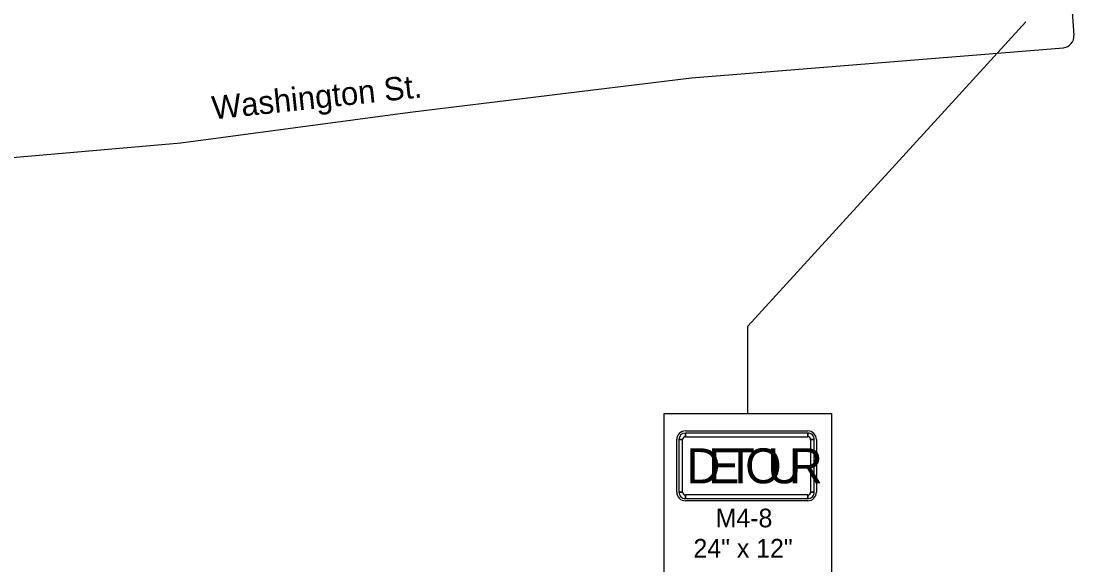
# Model space of a CAD drawing. Extents: x 10133 to 81668, y 6132 to 11018.
# Drawn here: x 11517.3 to 11970.2, y 8496.6 to 8730.4 of the extents above; entities that cross this region are included whole.
import ezdxf

# ---------------------------------------------------------------- set-up
doc = ezdxf.new("R2010")
doc.units = 0
for name, color, linetype in [('dsnTextFinalPlan', 7, 'Continuous'), ('Level 10', 7, 'Continuous'), ('Level 2', 7, 'Continuous'), ('Level 5', 7, 'Continuous')]:
    doc.layers.add(name, color=color, linetype=linetype)

msp = doc.modelspace()

# ---------------------------------------------------------------- linework, layer by layer
at = {"layer": 'dsnTextFinalPlan'}
for points in [[(11924.53, 9208.75), (11924.53, 9205.04), (11938.44, 9064.44), (11960.57, 8858.09), (11970.22, 8724.25)], [(11829.93, 8561.72), (11829.93, 8599.23), (11949.48, 8730.1)], [(10973.28, 8615.03), (11164.6, 8636.59), (11310.07, 8652.12), (11462.39, 8667.24), (11586.06, 8678), (11684.71, 8691.26), (11805.66, 8706.01), (11965.73, 8718.92)]]:
    msp.add_lwpolyline(points, dxfattribs=at)
msp.add_lwpolyline([(11793.9, 8561.72), (11865.97, 8561.72), (11865.97, 8249.49), (11793.9, 8249.49)], close=True, dxfattribs=at)
msp.add_lwpolyline([(11793.9, 8561.72), (11865.97, 8561.72), (11865.97, 8249.49), (11793.9, 8249.49)], close=True, dxfattribs=at)
msp.add_arc((11965.24, 8723.89), 5, 275.621, 4.1265, dxfattribs=at)
at = {"layer": 'Level 10'}
for p, q in [((11803.11, 8554.21), (11855.72, 8554.21)), ((11803.11, 8551.7), (11803.11, 8553.27)), ((11855.72, 8553.27), (11855.72, 8551.7)), ((11799.35, 8527.9), (11799.35, 8550.45)), ((11800.29, 8550.45), (11801.86, 8550.45)), ((11856.97, 8550.45), (11858.54, 8550.45)), ((11859.48, 8550.45), (11859.48, 8527.9)), ((11801.86, 8527.9), (11800.29, 8527.9)), ((11803.11, 8525.08), (11803.11, 8526.65)), ((11855.72, 8526.65), (11855.72, 8525.08)), ((11858.54, 8527.9), (11856.97, 8527.9)), ((11855.72, 8524.14), (11803.11, 8524.14))]:
    msp.add_line(p, q, dxfattribs=at)
for points in [[(11855.72, 8553.27), (11803.11, 8553.27), (11803.11, 8551.7), (11855.72, 8551.7), (11855.72, 8553.27)], [(11800.29, 8550.45), (11800.29, 8527.9), (11801.86, 8527.9), (11801.86, 8550.45), (11800.29, 8550.45)], [(11858.54, 8527.9), (11858.54, 8550.45), (11856.97, 8550.45), (11856.97, 8527.9), (11858.54, 8527.9)], [(11803.11, 8525.08), (11855.72, 8525.08), (11855.72, 8526.65), (11803.11, 8526.65), (11803.11, 8525.08)]]:
    msp.add_lwpolyline(points, close=True, dxfattribs=at)
for centre, radius, start, end in [((11803.11, 8550.45), 3.76, 90, 180), ((11803.11, 8550.45), 2.82, 90.0002, 179.9998), ((11855.72, 8550.45), 3.76, 0, 90), ((11855.72, 8550.45), 2.82, 0, 90.0002), ((11803.11, 8550.45), 1.25, 90.0002, 179.9998), ((11855.72, 8550.45), 1.25, 0, 90.0002), ((11803.11, 8527.9), 3.76, 180, 270), ((11803.11, 8527.9), 2.82, 179.9998, 270.0001), ((11803.11, 8527.9), 1.25, 179.9998, 270.0001), ((11855.72, 8527.9), 2.82, 270.0001, 0.0003), ((11855.72, 8527.9), 1.25, 270.0001, 0.0003), ((11855.72, 8527.9), 3.76, 270, 359.9911)]:
    msp.add_arc(centre, radius, start, end, dxfattribs=at)

# ---------------------------------------------------------------- texts
for s, p in [('D', (11803.59, 8531.66)), ('E', (11812.83, 8531.66)), ('T', (11820.61, 8531.66)), ('O', (11828.82, 8531.66)), ('U', (11838.41, 8531.66)), ('R', (11847.65, 8531.66))]:
    msp.add_text(s, height=15.03, dxfattribs=at).set_placement(p)
at = {"layer": 'Level 2'}
msp.add_text('Washington St.', height=10, rotation=6.0477, dxfattribs=at).set_placement((11599.92, 8688.05))
at = {"layer": 'Level 5'}
for s, p in [('M4-8', (11816.12, 8512.76)), ('24" x 12"', (11806.56, 8499.76))]:
    msp.add_text(s, height=8, dxfattribs=at).set_placement(p)

doc.saveas('drawing.dxf')
